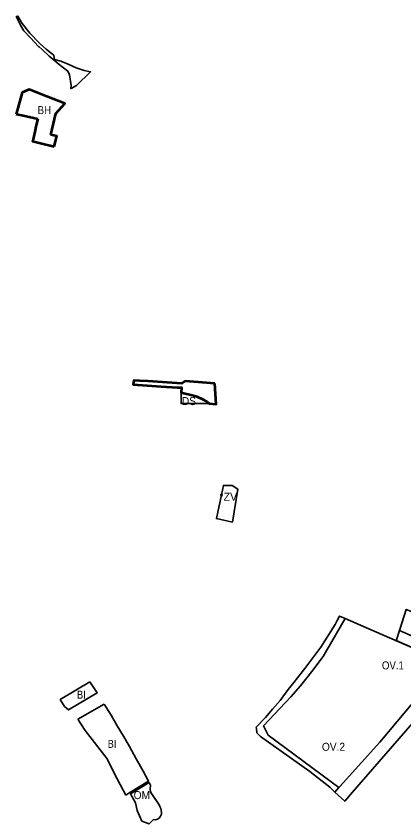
# Model space of a CAD drawing. Extents: x -650276 to -642489, y -1074311 to -1066658.
# Drawn here: x -646702 to -646121, y -1071668 to -1070457 of the extents above; entities that cross this region are included whole.
import ezdxf

# ---------------------------------------------------------------- set-up
doc = ezdxf.new("R2010")
doc.units = 0
doc.header["$LTSCALE"] = 4.8
doc.header["$PDMODE"] = 32
doc.header["$PDSIZE"] = 2.4
for name, color, linetype, lineweight in [('1', 7, 'Continuous', 35), ('11', 7, 'Continuous', 35), ('12', 7, 'Continuous', 35), ('15', 7, 'Continuous', 35), ('2', 7, 'Continuous', 35), ('24', 7, 'Continuous', 35), ('40', 7, 'Continuous', 35), ('60', 7, 'Continuous', 53)]:
    doc.layers.add(name, color=color, linetype=linetype, lineweight=lineweight)
doc.layers.add('62', color=7, linetype='Continuous')
doc.layers.add('63', color=7, linetype='Continuous')

msp = doc.modelspace()

# ---------------------------------------------------------------- linework, layer by layer
at = {"layer": '1'}
msp.add_line((-646665.42, -1070647.54), (-646645.03, -1070652.34), dxfattribs=at)
for points in [[(-646655.95, -1070577.64), (-646682.29, -1070567.36), (-646692.98, -1070571.45), (-646701.87, -1070603.92)], [(-646649.71, -1070634.85), (-646642.32, -1070603.3), (-646628.69, -1070588.27), (-646655.95, -1070577.64)], [(-646701.87, -1070603.92), (-646693.18, -1070605.83), (-646669.59, -1070611.01), (-646672.13, -1070622.41), (-646673.91, -1070630.38), (-646676.414, -1070641.58)], [(-646645.03, -1070652.34), (-646641.09, -1070636.89), (-646649.71, -1070634.85)], [(-646676.414, -1070641.58), (-646676.81, -1070643.36), (-646677.13, -1070644.78), (-646665.42, -1070647.54)]]:
    msp.add_lwpolyline(points, dxfattribs=at)
at = {"layer": '11'}
msp.add_lwpolyline([(-646066.165, -1071422.155), (-646153.5, -1071383.85), (-646208.577, -1071360.044), (-646241.68, -1071416.887), (-646258.487, -1071439.265), (-646275.615, -1071460.886), (-646289.976, -1071477.514), (-646330.914, -1071521.11), (-646324, -1071535), (-646217.978, -1071613.552), (-646211.407, -1071606.247), (-646156.471, -1071545.166), (-646094.063, -1071471.007)], close=True, dxfattribs=at)
at = {"layer": '12'}
msp.add_lwpolyline([(-646502.39, -1071605.72), (-646530.27, -1071622.79), (-646522.99, -1071636.22), (-646520.32, -1071647.59), (-646513.43, -1071663.64), (-646502.53, -1071667.82), (-646496.06, -1071661.5), (-646492.89, -1071661.75), (-646490.07, -1071660.88), (-646487.36, -1071659.1), (-646485.29, -1071656.53), (-646484.15, -1071653.38), (-646483.97, -1071650.63), (-646484.38, -1071647.41), (-646485.2, -1071644.85), (-646486.31, -1071641.97), (-646487.56, -1071639.23), (-646497.83, -1071624.02), (-646499.829, -1071620.704), (-646500.289, -1071619.291), (-646500.83, -1071615.62), (-646500.34, -1071609.66)], close=True, dxfattribs=at)
at = {"layer": '15'}
for points in [[(-646623.95, -1070529.36), (-646634.85, -1070524.43), (-646644.2, -1070522.08), (-646645.31, -1070515.85), (-646654, -1070509), (-646656.83, -1070506.66), (-646665.457, -1070499.019), (-646667.42, -1070497.28), (-646681.6, -1070482.89), (-646692.74, -1070468.28), (-646699.26, -1070457.2), (-646701.65, -1070457.93), (-646693.119, -1070474.009), (-646690.316, -1070479.212), (-646680.44, -1070489.669), (-646668.361, -1070502.459), (-646667.369, -1070503.36), (-646662.895, -1070507.428), (-646652.352, -1070517.013), (-646643.895, -1070524.284), (-646637.158, -1070529.564), (-646624.211, -1070539.711), (-646621.729, -1070545.248), (-646619.34, -1070560.95), (-646619.99, -1070565.54), (-646619.15, -1070565.53), (-646611.41, -1070560.96), (-646590.2, -1070540.66), (-646599.81, -1070538.51), (-646611.88, -1070534.82)], [(-646275.615, -1071460.886), (-646258.487, -1071439.265), (-646241.68, -1071416.887), (-646208.577, -1071360.044), (-646217.049, -1071356.382), (-646220.61, -1071363.16), (-646223.77, -1071369.24), (-646245.1, -1071403.04), (-646269.2, -1071435.22), (-646281.99, -1071451.4), (-646283.52, -1071453.34), (-646293.87, -1071466.43), (-646306.14, -1071482.86), (-646317.52, -1071496.12), (-646327.97, -1071508.29), (-646341.88, -1071522.81), (-646341.66, -1071524.87), (-646340.93, -1071531.64), (-646335.3, -1071537.05), (-646261.46, -1071589.38), (-646231.43, -1071613.06), (-646223.928, -1071620.168), (-646217.978, -1071613.552), (-646324, -1071535), (-646330.914, -1071521.11), (-646289.976, -1071477.514), (-646275.615, -1071460.886)]]:
    msp.add_lwpolyline(points, close=True, dxfattribs=at)
for points in [[(-646058.719, -1071407.796), (-646127.301, -1071378.036), (-646131.79, -1071391.83), (-646132.229, -1071393.179), (-646066.165, -1071422.155)], [(-646094.063, -1071471.007), (-646156.471, -1071545.166), (-646211.407, -1071606.247), (-646223.928, -1071620.168), (-646209.322, -1071634.004), (-646197.398, -1071620.579), (-646077.593, -1071482.499)]]:
    msp.add_lwpolyline(points, dxfattribs=at)
at = {"layer": '2'}
msp.add_line((-646609.21, -1071510.98), (-646570, -1071488.38), dxfattribs=at)
msp.add_lwpolyline([(-646591.65, -1071454.91), (-646635.79, -1071481.6), (-646629.37, -1071491.74), (-646623.18, -1071496.99), (-646580.58, -1071471.48)], close=True, dxfattribs=at)
for points in [[(-646570, -1071488.38), (-646559.53, -1071505.12), (-646550.23, -1071520.88), (-646541.14, -1071536.3), (-646532.04, -1071551.72), (-646521.8, -1071570.34), (-646511.47, -1071589.11), (-646503.31, -1071603.95), (-646531.2, -1071621.07), (-646537.28, -1071624.8)], [(-646537.28, -1071624.8), (-646545.89, -1071609.07), (-646555.78, -1071589.66), (-646565.17, -1071570.4), (-646598.63, -1071527.8), (-646609.21, -1071510.98)]]:
    msp.add_lwpolyline(points, dxfattribs=at)
at = {"layer": '24'}
for points in [[(-646454.59, -1071021.54), (-646454.59, -1071038), (-646412.54, -1071038.01), (-646415.61, -1071035.4), (-646421.58, -1071031.81), (-646430.91, -1071027.44)], [(-646045.393, -1071385.64), (-646040.084, -1071376.813), (-646117.031, -1071346.48), (-646127.301, -1071378.036), (-646058.719, -1071407.796)]]:
    msp.add_lwpolyline(points, close=True, dxfattribs=at)
at = {"layer": '40'}
for points in [[(-646377.5, -1071215.56), (-646369.76, -1071166.06), (-646377.87, -1071160.66), (-646391.07, -1071160.52), (-646394.05, -1071174.83)], [(-646394.05, -1071174.83), (-646401.64, -1071210.18), (-646377.5, -1071215.56)]]:
    msp.add_lwpolyline(points, dxfattribs=at)
msp.add_point((-646394.05, -1071174.83), dxfattribs=at)
at = {"layer": '60'}
for points in [[(-646655.95, -1070577.64), (-646682.29, -1070567.36), (-646692.98, -1070571.45), (-646701.87, -1070603.92)], [(-646649.71, -1070634.85), (-646642.32, -1070603.3), (-646628.69, -1070588.27), (-646655.95, -1070577.64)], [(-646701.87, -1070603.92), (-646693.18, -1070605.83), (-646669.59, -1070611.01)], [(-646669.59, -1070611.01), (-646672.13, -1070622.41), (-646673.91, -1070630.38), (-646676.414, -1070641.58)], [(-646645.03, -1070652.34), (-646641.09, -1070636.89), (-646649.71, -1070634.85)], [(-646676.414, -1070641.58), (-646676.81, -1070643.36), (-646677.13, -1070644.78), (-646665.42, -1070647.54), (-646645.03, -1070652.34)]]:
    msp.add_lwpolyline(points, dxfattribs=at)
msp.add_lwpolyline([(-646403.81, -1071007.7), (-646435.28, -1071005.2), (-646448.48, -1071004.25), (-646453.7, -1071007.79), (-646504.25, -1071004.54), (-646516.78, -1071003.78), (-646525.4, -1071003.29), (-646526.31, -1071009.55), (-646484.27, -1071012.11), (-646460.09, -1071013.61), (-646454.02, -1071013.98), (-646454.59, -1071021.54), (-646436.15, -1071025.97), (-646430.91, -1071027.44), (-646421.58, -1071031.81), (-646415.61, -1071035.4), (-646412.54, -1071038.01), (-646402.09, -1071038.95)], close=True, dxfattribs=at)

# ---------------------------------------------------------------- texts
at = {"layer": '62'}
for s, width, p in [('DS', 0.95, (-646453.386, -1071040.148)), ('OV.1', 0.9, (-646153.486, -1071436.306)), ('BI', 0.85, (-646610.515, -1071480.22)), ('BI', 0.85, (-646564.529, -1071553.971)), ('OV.2', 0.95, (-646243.486, -1071558.306)), ('OM', 0.95, (-646525.703, -1071630.756))]:
    msp.add_text(s, height=12, dxfattribs=dict(at, width=width)).set_placement(p)
msp.add_text('ZV', height=12, dxfattribs=at).set_placement((-646390.931, -1071183.591))
at = {"layer": '63', "width": 0.9}
msp.add_text('BH', height=12, dxfattribs=at).set_placement((-646669.646, -1070604.101))

doc.saveas('drawing.dxf')
